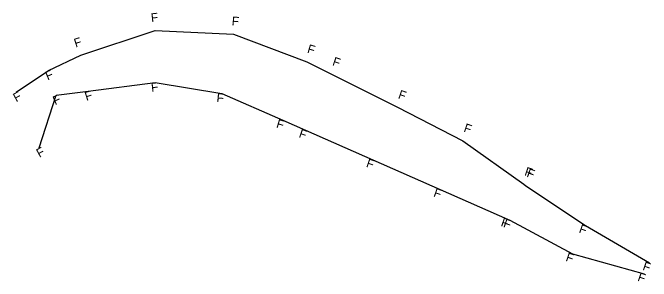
# Model space of a CAD drawing. Extents: x -26 to 2348728, y -10 to 843971.
# Drawn here: x 2348294 to 2348728, y 843787.9 to 843970.6 of the extents above; entities that cross this region are included whole.
import ezdxf

# ---------------------------------------------------------------- set-up
doc = ezdxf.new("R2010")
doc.units = 0
for name, color, linetype in [('Prop SS Cut Text', 7, 'Continuous'), ('Prop SS Fill Line', 7, 'Continuous'), ('Prop SS Fill Text', 7, 'Continuous')]:
    doc.layers.add(name, color=color, linetype=linetype)

msp = doc.modelspace()

# ---------------------------------------------------------------- linework, layer by layer
at = {"layer": 'Prop SS Fill Line'}
for p, q in [((2348340.34, 843941.8), (2348390.78, 843958.47)), ((2348390.78, 843958.47), (2348444.06, 843956.08)), ((2348444.06, 843956.08), (2348493.92, 843937.27)), ((2348318.3, 843931.28), (2348340.34, 843941.8)), ((2348493.92, 843937.27), (2348510.74, 843928.78)), ((2348296.22, 843916.5), (2348318.3, 843931.28)), ((2348510.74, 843928.78), (2348555.44, 843906.31)), ((2348345.28, 843917.27), (2348390.83, 843923.1)), ((2348390.83, 843923.1), (2348436.06, 843915.64)), ((2348323.36, 843914.47), (2348345.28, 843917.27)), ((2348436.06, 843915.64), (2348477.46, 843897.46)), ((2348312, 843878.69), (2348323.36, 843914.47)), ((2348555.44, 843906.31), (2348600, 843883.56)), ((2348477.46, 843897.46), (2348492.99, 843890.63)), ((2348492.99, 843890.63), (2348538.77, 843870.51)), ((2348600, 843883.56), (2348641.34, 843853.89)), ((2348538.77, 843870.51), (2348584.56, 843850.4)), ((2348584.56, 843850.4), (2348630.35, 843830.27)), ((2348641.34, 843853.89), (2348642.84, 843852.87)), ((2348642.84, 843852.87), (2348683.4, 843825.77)), ((2348630.35, 843830.27), (2348631.99, 843829.55)), ((2348631.99, 843829.55), (2348674.43, 843806.5)), ((2348683.4, 843825.77), (2348726.72, 843800.35)), ((2348674.43, 843806.5), (2348723.28, 843792.97))]:
    msp.add_line(p, q, dxfattribs=at)

# ---------------------------------------------------------------- texts
at = {"layer": 'Prop SS Cut Text'}
for rotation, p in [(6.0924, (2348388.18, 843964.2)), (354.8136, (2348442.63, 843962.2)), (17.371, (2348336.68, 843946.91)), (343.535, (2348493.72, 843943.55)), (341.0369, (2348510.82, 843935.06)), (341.0369, (2348555.51, 843912.59)), (341.0369, (2348600.07, 843889.84)), (341.0369, (2348641.41, 843860.17)), (341.0369, (2348642.92, 843859.16))]:
    msp.add_text('F', height=6, rotation=rotation, dxfattribs=at).set_placement(p)
at = {"layer": 'Prop SS Fill Text'}
for rotation, p in [(22.7397, (2348317.63, 843924.53)), (6.0924, (2348388.26, 843916.82)), (28.6497, (2348296.25, 843909.72)), (22.7397, (2348322.69, 843907.72)), (17.371, (2348343.98, 843910.62)), (354.8136, (2348432.31, 843909.99)), (343.535, (2348472.68, 843892.65)), (341.0369, (2348488, 843886.04)), (28.6497, (2348312.03, 843871.91)), (341.0369, (2348533.78, 843865.91)), (341.0369, (2348579.57, 843845.8)), (341.0369, (2348625.36, 843825.68)), (341.0369, (2348627, 843824.96)), (341.0369, (2348678.41, 843821.18)), (341.0369, (2348669.44, 843801.91)), (341.0369, (2348721.73, 843795.75)), (341.0369, (2348718.29, 843788.37))]:
    msp.add_text('F', height=6, rotation=rotation, dxfattribs=at).set_placement(p)

doc.saveas('drawing.dxf')
